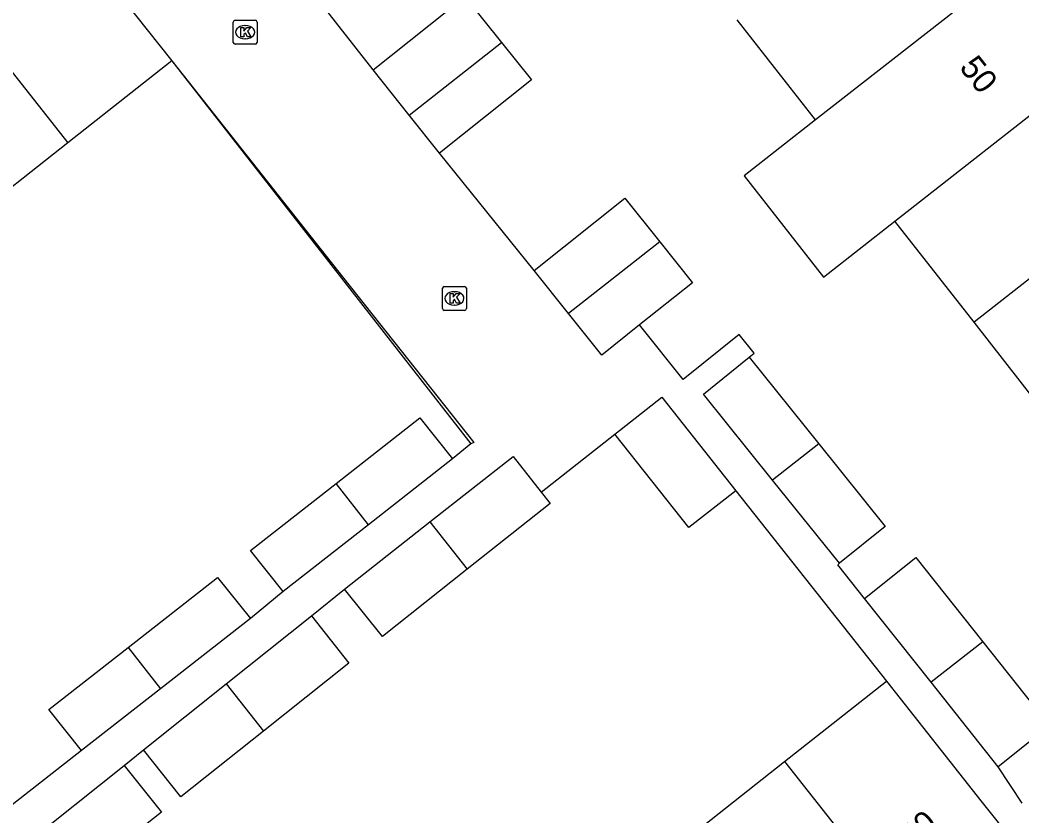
# Model space of a CAD drawing. Extents: x 160379 to 161131, y 383940 to 384849.
# Drawn here: x 160719.33 to 160761.36, y 384329.72 to 384363.11 of the extents above; entities that cross this region are included whole.
import ezdxf

# ---------------------------------------------------------------- set-up
doc = ezdxf.new("R2010")
doc.units = 0
for name, color, linetype in [('IMGEO_Kolk', 7, 'Continuous'), ('IMGEO_Muur', 7, 'Continuous'), ('IMGEO_Pand', 7, 'Continuous'), ('IMGEO_Pand_nummerreeks', 7, 'Continuous'), ('IMGEO_Voetpad_open', 7, 'Continuous')]:
    doc.layers.add(name, color=color, linetype=linetype)

msp = doc.modelspace()

# ---------------------------------------------------------------- linework, layer by layer
at = {"layer": 'IMGEO_Kolk'}
for p, q in [((160728.351, 384363.098), (160729.203, 384363.098)), ((160728.276, 384362.172), (160728.276, 384363.024)), ((160728.764, 384362.878), (160728.789, 384362.878)), ((160729.277, 384363.024), (160729.277, 384362.172)), ((160728.787, 384362.318), (160728.762, 384362.318)), ((160729.203, 384362.098), (160728.351, 384362.098)), ((160737.052, 384351.005), (160737.052, 384351.857)), ((160737.127, 384351.931), (160737.979, 384351.931)), ((160738.053, 384351.857), (160738.053, 384351.005)), ((160737.54, 384351.711), (160737.565, 384351.711)), ((160737.979, 384350.931), (160737.127, 384350.931)), ((160737.563, 384351.151), (160737.538, 384351.151))]:
    msp.add_line(p, q, dxfattribs=at)
for points in [[(160728.351, 384363.098), (160729.203, 384363.098)], [(160728.276, 384362.172), (160728.276, 384363.024)], [(160728.597, 384362.798), (160728.72, 384362.798), (160728.72, 384362.647), (160728.85, 384362.798), (160729.014, 384362.798), (160728.868, 384362.647), (160729.021, 384362.398), (160728.869, 384362.398), (160728.784, 384362.562), (160728.72, 384362.495), (160728.72, 384362.398), (160728.597, 384362.398), (160728.597, 384362.798)], [(160729.277, 384363.024), (160729.277, 384362.172)], [(160729.203, 384362.098), (160728.351, 384362.098)], [(160737.052, 384351.005), (160737.052, 384351.857)], [(160737.127, 384351.931), (160737.979, 384351.931)], [(160738.053, 384351.857), (160738.053, 384351.005)], [(160737.373, 384351.631), (160737.496, 384351.631), (160737.496, 384351.48), (160737.626, 384351.631), (160737.79, 384351.631), (160737.644, 384351.48), (160737.797, 384351.231), (160737.645, 384351.231), (160737.56, 384351.395), (160737.496, 384351.328), (160737.496, 384351.231), (160737.373, 384351.231), (160737.373, 384351.631)], [(160737.979, 384350.931), (160737.127, 384350.931)]]:
    msp.add_lwpolyline(points, dxfattribs=at)
for centre, start, end in [((160728.353, 384363.022), 91.552, 178.448), ((160728.353, 384363.022), 91.552, 178.448), ((160729.201, 384363.022), 1.552, 88.448), ((160729.201, 384363.022), 1.552, 88.448), ((160728.353, 384362.174), 181.552, 268.448), ((160728.353, 384362.174), 181.552, 268.448), ((160729.201, 384362.174), 271.552, 358.448), ((160729.201, 384362.174), 271.552, 358.448), ((160737.129, 384351.855), 91.552, 178.448), ((160737.129, 384351.855), 91.552, 178.448), ((160737.977, 384351.855), 1.552, 88.448), ((160737.977, 384351.855), 1.552, 88.448), ((160737.129, 384351.007), 181.552, 268.448), ((160737.129, 384351.007), 181.552, 268.448), ((160737.977, 384351.007), 271.552, 358.448), ((160737.977, 384351.007), 271.552, 358.448)]:
    msp.add_arc(centre, 0.0765, start, end, dxfattribs=at)
for centre, major_axis, ratio, start_param, end_param in [((160728.763, 384362.598), (-0.387, 0.002), 0.722429, 4.712389, 7.853982), ((160728.788, 384362.598), (-0.39, 0.002), 0.717154, 1.570796, 4.712389), ((160737.539, 384351.431), (-0.387, 0.002), 0.722429, 4.712389, 7.853982), ((160737.564, 384351.431), (-0.39, 0.002), 0.717154, 1.570796, 4.712389)]:
    msp.add_ellipse(centre, major_axis=major_axis, ratio=ratio, start_param=start_param, end_param=end_param, dxfattribs=at)
at = {"layer": 'IMGEO_Muur'}
msp.add_lwpolyline([(160725.695, 384361.391), (160738.244, 384345.329), (160737.476, 384344.698)], dxfattribs=at)
at = {"layer": 'IMGEO_Pand'}
for points in [[(160721.038, 384367.273), (160724.173, 384363.313), (160725.695, 384361.391)], [(160714.734, 384366.337), (160721.335, 384357.957)], [(160761.277, 384365.634), (160752.701, 384358.916)], [(160734.14, 384361.019), (160737.99, 384364.092), (160739.533, 384362.16)], [(160752.701, 384358.916), (160749.409, 384363.118)], [(160735.654, 384359.121), (160739.533, 384362.16)], [(160739.533, 384362.16), (160740.781, 384360.596), (160736.931, 384357.523)], [(160725.695, 384361.391), (160721.335, 384357.957)], [(160735.654, 384359.121), (160734.14, 384361.019)], [(160756.024, 384354.672), (160763.454, 384360.491)], [(160736.931, 384357.523), (160735.654, 384359.121)], [(160752.701, 384358.916), (160749.708, 384356.573), (160753.031, 384352.329), (160756.024, 384354.672)], [(160721.335, 384357.957), (160716.971, 384354.519)], [(160766.777, 384356.248), (160759.348, 384350.429)], [(160740.897, 384352.596), (160744.707, 384355.638), (160746.172, 384353.802)], [(160759.348, 384350.429), (160756.024, 384354.672)], [(160746.172, 384353.802), (160742.334, 384350.795)], [(160746.172, 384353.802), (160747.54, 384352.089), (160745.32, 384350.317)], [(160742.334, 384350.795), (160740.897, 384352.596)], [(160745.32, 384350.317), (160743.73, 384349.047), (160742.334, 384350.795)], [(160762.672, 384346.186), (160759.348, 384350.429)], [(160750.897, 384343.809), (160747.995, 384347.419), (160749.92, 384348.967)], [(160749.92, 384348.967), (160752.841, 384345.332)], [(160744.281, 384345.742), (160746.249, 384347.284), (160749.349, 384343.365)], [(160732.589, 384343.67), (160736.098, 384346.421), (160737.476, 384344.698)], [(160749.349, 384343.365), (160747.381, 384341.823), (160744.281, 384345.742)], [(160752.841, 384345.332), (160750.897, 384343.809)], [(160752.841, 384345.332), (160755.626, 384341.866), (160753.701, 384340.319)], [(160737.476, 384344.698), (160733.954, 384341.937)], [(160736.522, 384342.054), (160740.011, 384344.804), (160741.198, 384343.303)], [(160753.701, 384340.319), (160750.897, 384343.809)], [(160730.375, 384339.132), (160728.997, 384340.855), (160732.589, 384343.67)], [(160733.954, 384341.937), (160732.589, 384343.67)], [(160741.198, 384343.303), (160741.57, 384342.833), (160738.089, 384340.068)], [(160732.947, 384339.237), (160736.522, 384342.054)], [(160736.522, 384342.054), (160738.089, 384340.068)], [(160733.954, 384341.937), (160730.375, 384339.132)], [(160754.752, 384338.846), (160756.908, 384340.558), (160759.715, 384337.024)], [(160738.089, 384340.068), (160734.536, 384337.245), (160732.947, 384339.237)], [(160723.863, 384336.79), (160727.621, 384339.728), (160728.999, 384338.005)], [(160757.547, 384335.327), (160754.752, 384338.846)], [(160728.999, 384338.005), (160725.228, 384335.057)], [(160727.986, 384335.264), (160731.553, 384338.11)], [(160731.553, 384338.11), (160733.127, 384336.126), (160729.549, 384333.283)], [(160759.715, 384337.024), (160757.547, 384335.327)], [(160759.715, 384337.024), (160762.515, 384333.499), (160760.359, 384331.787)], [(160721.914, 384332.466), (160720.536, 384334.189), (160723.863, 384336.79)], [(160723.863, 384336.79), (160725.228, 384335.057)], [(160751.4, 384332.004), (160755.67, 384335.373)], [(160755.67, 384335.373), (160757.964, 384332.47), (160759.638, 384330.352), (160761.067, 384328.549)], [(160760.359, 384331.787), (160757.547, 384335.327)], [(160725.228, 384335.057), (160721.914, 384332.466)], [(160724.514, 384332.494), (160727.986, 384335.264)], [(160727.986, 384335.264), (160729.549, 384333.283)], [(160729.549, 384333.283), (160726.08, 384330.527), (160724.514, 384332.494)], [(160747.119, 384328.627), (160751.4, 384332.004)], [(160751.4, 384332.004), (160757.988, 384323.659)], [(160721.037, 384326.521), (160719.491, 384328.486), (160723.697, 384331.842)], [(160723.697, 384331.842), (160725.266, 384329.88), (160721.037, 384326.521)]]:
    msp.add_lwpolyline(points, dxfattribs=at)
at = {"layer": 'IMGEO_Voetpad_open'}
for points in [[(160734.14, 384361.019), (160730.277, 384365.967)], [(160725.695, 384361.391), (160732.864, 384352.338), (160738.363, 384345.393), (160738.244, 384345.329), (160737.476, 384344.698)], [(160740.897, 384352.596), (160736.931, 384357.523)], [(160749.92, 384348.967), (160750.124, 384349.131), (160749.492, 384349.918), (160747.144, 384348.032), (160745.32, 384350.317)], [(160741.198, 384343.303), (160744.281, 384345.742)], [(160749.349, 384343.365), (160755.67, 384335.373)], [(160754.752, 384338.846), (160753.628, 384340.261), (160753.701, 384340.319)], [(160730.375, 384339.132), (160728.999, 384338.005)], [(160731.553, 384338.11), (160732.947, 384339.237)], [(160721.914, 384332.466), (160718.478, 384329.78), (160717.944, 384330.463), (160717.382, 384330.138)], [(160723.697, 384331.842), (160724.514, 384332.494)], [(160761.367, 384330.263), (160760.359, 384331.787)]]:
    msp.add_lwpolyline(points, dxfattribs=at)

# ---------------------------------------------------------------- texts
at = {"layer": 'IMGEO_Pand_nummerreeks'}
for s, rotation, p in [('50', 308.2619, (160758.697, 384361.109)), ('60', 38.2881, (160756.72, 384328.328))]:
    msp.add_text(s, height=1, rotation=rotation, dxfattribs=at).set_placement(p)

doc.saveas('drawing.dxf')
